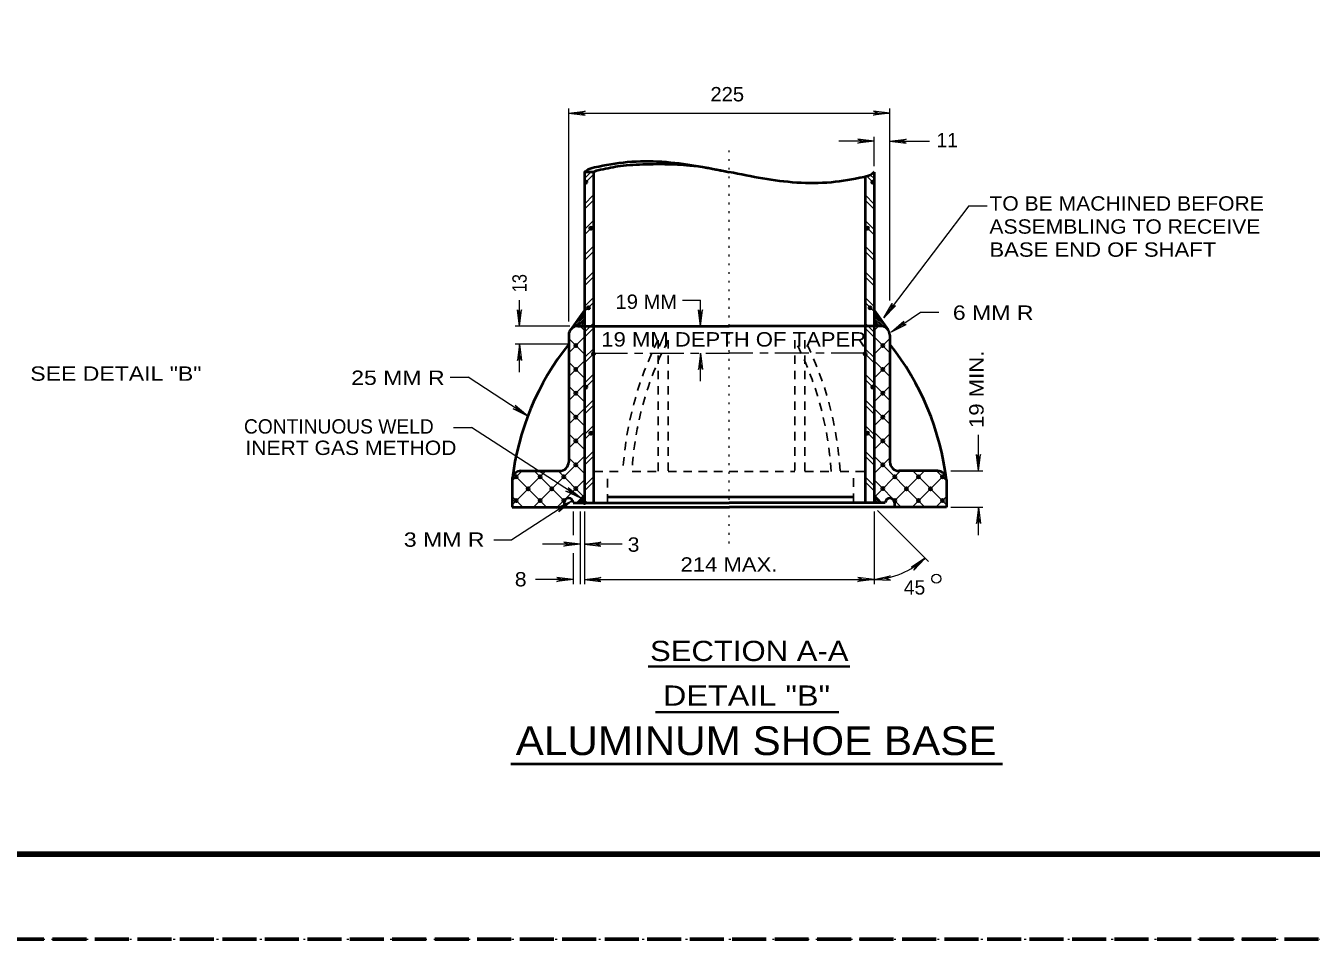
# Model space of a CAD drawing. Extents: x 312583 to 312854, y 144419 to 144597.
# Drawn here: x 312655 to 312723.1, y 144418.6 to 144466.9 of the extents above; entities that cross this region are included whole.
import ezdxf
from ezdxf.enums import TextEntityAlignment as Align

# ---------------------------------------------------------------- set-up
doc = ezdxf.new("R2010")
doc.units = 0
doc.header["$LTSCALE"] = 0.3
doc.header["$PDMODE"] = 32
doc.header["$PDSIZE"] = 0.15
for name, pattern in [('DOTTED', [1.5, 0.3, -1.2]), ('LONG_DASH_SHORT_DASH', [9.9, 6, -1.2, 1.5, -1.2]), ('LONG_DASHED', [7.5, 6, -1.5]), ('SHORT_DASHED', [2.7, 1.5, -1.2])]:
    doc.linetypes.add(name, pattern=pattern)
for name, color, linetype, lineweight in [('1', 7, 'Continuous', 35), ('2', 7, 'Continuous', 13), ('62', 7, 'DOTTED', 13), ('63', 7, 'LONG_DASHED', 60)]:
    doc.layers.add(name, color=color, linetype=linetype, lineweight=lineweight)

msp = doc.modelspace()

# ---------------------------------------------------------------- linework, layer by layer
at = {"layer": '1', "lineweight": 40}
for p, q in [((312684.6288, 144459.1856), (312684.6288, 144441.6903)), ((312685.1118, 144459.1856), (312684.6288, 144459.1856)), ((312685.1118, 144459.1856), (312685.1118, 144441.6903)), ((312699.9621, 144459.1856), (312699.9621, 144441.6903)), ((312699.4868, 144458.9326), (312699.4868, 144441.6903)), ((312684.6288, 144451.8716), (312683.8851, 144450.8366)), ((312699.9621, 144451.8716), (312700.7135, 144450.8366)), ((312684.2685, 144451.036), (312684.6288, 144451.036)), ((312684.6288, 144451.036), (312692.2955, 144451.036)), ((312699.9621, 144451.036), (312692.2955, 144451.036)), ((312700.3225, 144451.036), (312699.9621, 144451.036)), ((312683.7931, 144450.5606), (312683.7931, 144443.8523)), ((312700.7978, 144450.5606), (312700.7978, 144443.8523)), ((312680.7955, 144442.894), (312680.7955, 144441.4526)), ((312681.2785, 144443.3693), (312683.3101, 144443.3693)), ((312703.3201, 144443.3693), (312701.2808, 144443.3693)), ((312703.7955, 144442.894), (312703.7955, 144441.4526)), ((312684.2608, 144441.6903), (312684.6288, 144442.066)), ((312700.3301, 144441.6903), (312699.9621, 144442.066)), ((312680.7955, 144441.4526), (312692.2955, 144441.4526)), ((312683.5555, 144441.6903), (312683.5555, 144441.4526)), ((312684.0308, 144441.6903), (312692.2955, 144441.6903)), ((312685.8401, 144442.0046), (312698.8658, 144442.0046)), ((312700.5601, 144441.6903), (312692.2955, 144441.6903)), ((312703.7955, 144441.4526), (312692.2955, 144441.4526)), ((312701.0431, 144441.6903), (312701.0431, 144441.4526))]:
    msp.add_line(p, q, dxfattribs=at)
at = {"layer": '1', "lineweight": 13}
for p, q in [((312684.6288, 144458.8483), (312684.9661, 144459.1856)), ((312684.6288, 144458.58), (312685.1118, 144459.0553)), ((312699.9621, 144458.58), (312699.5941, 144458.948)), ((312699.9621, 144458.8483), (312699.7628, 144459.0476)), ((312684.6288, 144457.4913), (312685.1118, 144457.9743)), ((312699.9621, 144457.4913), (312699.4868, 144457.9743)), ((312684.6288, 144457.223), (312685.1118, 144457.706)), ((312699.9621, 144457.223), (312699.4868, 144457.706)), ((312684.6288, 144456.142), (312685.1118, 144456.6173)), ((312699.9621, 144456.142), (312699.4868, 144456.6173)), ((312684.6288, 144455.866), (312685.1118, 144456.349)), ((312699.9621, 144455.866), (312699.4868, 144456.349)), ((312684.6288, 144454.785), (312685.1118, 144455.2603)), ((312699.9621, 144454.785), (312699.4868, 144455.2603)), ((312684.6288, 144454.509), (312685.1118, 144454.992)), ((312699.9621, 144454.509), (312699.4868, 144454.992)), ((312684.6288, 144453.428), (312685.1118, 144453.911)), ((312684.6288, 144453.1596), (312685.1118, 144453.635)), ((312699.9621, 144453.428), (312699.4868, 144453.911)), ((312699.9621, 144453.1596), (312699.4868, 144453.635)), ((312684.6288, 144452.071), (312685.1118, 144452.554)), ((312684.6288, 144451.8026), (312685.1118, 144452.278)), ((312699.9621, 144452.071), (312699.4868, 144452.554)), ((312699.9621, 144451.8026), (312699.4868, 144452.278)), ((312684.6288, 144450.806), (312684.3988, 144451.036)), ((312684.6288, 144450.714), (312685.1041, 144451.197)), ((312684.6288, 144450.4456), (312685.1041, 144450.9286)), ((312699.9621, 144450.714), (312699.4868, 144451.197)), ((312699.9621, 144450.4456), (312699.4868, 144450.9286)), ((312699.9621, 144450.806), (312700.1921, 144451.036)), ((312683.7931, 144449.6176), (312684.6288, 144450.461)), ((312684.6288, 144449.541), (312683.7931, 144450.3843)), ((312700.7978, 144449.6176), (312699.9621, 144450.461)), ((312699.9621, 144449.541), (312700.7978, 144450.3843)), ((312684.6288, 144449.3646), (312685.1118, 144449.84)), ((312684.6288, 144449.0886), (312685.1118, 144449.5716)), ((312699.9621, 144449.3646), (312699.4868, 144449.84)), ((312699.9621, 144449.0886), (312699.4868, 144449.5716)), ((312683.7931, 144448.3603), (312684.6288, 144449.196)), ((312684.6288, 144448.2836), (312683.7931, 144449.1193)), ((312700.7978, 144448.3603), (312699.9621, 144449.196)), ((312699.9621, 144448.2836), (312700.7978, 144449.1193)), ((312684.6288, 144448.0076), (312685.1118, 144448.483)), ((312684.6288, 144447.7393), (312685.1118, 144448.2146)), ((312699.9621, 144448.0076), (312699.4868, 144448.483)), ((312699.9621, 144447.7393), (312699.4868, 144448.2146)), ((312683.7931, 144447.0953), (312684.6288, 144447.9386)), ((312684.6288, 144447.0186), (312683.7931, 144447.8543)), ((312700.7978, 144447.0953), (312699.9621, 144447.9386)), ((312699.9621, 144447.0186), (312700.7978, 144447.8543)), ((312684.6288, 144446.6506), (312685.1118, 144447.1336)), ((312684.6288, 144446.3823), (312685.1118, 144446.8576)), ((312699.9621, 144446.6506), (312699.4868, 144447.1336)), ((312699.9621, 144446.3823), (312699.4868, 144446.8576)), ((312683.7931, 144445.838), (312684.6288, 144446.6813)), ((312684.6288, 144445.7536), (312683.7931, 144446.597)), ((312700.7978, 144445.838), (312699.9621, 144446.6813)), ((312699.9621, 144445.7536), (312700.7978, 144446.597)), ((312684.6288, 144445.2936), (312685.1118, 144445.7766)), ((312684.6288, 144445.0253), (312685.1118, 144445.5083)), ((312699.9621, 144445.2936), (312699.4868, 144445.7766)), ((312699.9621, 144445.0253), (312699.4868, 144445.5083)), ((312683.7931, 144444.5806), (312684.6288, 144445.4163)), ((312684.6288, 144444.4963), (312683.7931, 144445.332)), ((312700.7978, 144444.5806), (312699.9621, 144445.4163)), ((312699.9621, 144444.4963), (312700.7978, 144445.332)), ((312681.9301, 144441.4526), (312684.6288, 144444.159)), ((312684.6288, 144443.9443), (312685.1118, 144444.4196)), ((312684.6288, 144443.6683), (312685.1118, 144444.1513)), ((312699.9621, 144443.9443), (312699.4868, 144444.4196)), ((312699.9621, 144443.6683), (312699.4868, 144444.1513)), ((312702.6608, 144441.4526), (312699.9621, 144444.159)), ((312684.6288, 144443.2313), (312683.7931, 144444.067)), ((312699.9621, 144443.2313), (312700.7978, 144444.067)), ((312680.7955, 144441.583), (312682.5818, 144443.3693)), ((312680.7955, 144442.8403), (312681.3245, 144443.3693)), ((312682.6201, 144441.4526), (312680.7955, 144443.2773)), ((312683.5631, 144441.767), (312681.9685, 144443.3693)), ((312683.1875, 144441.4526), (312684.6288, 144442.894)), ((312684.6288, 144441.9663), (312683.2258, 144443.3693)), ((312684.6288, 144442.5873), (312685.1118, 144443.0626)), ((312684.6288, 144442.3113), (312685.1118, 144442.7943)), ((312699.9621, 144442.5873), (312699.4868, 144443.0626)), ((312699.9621, 144442.3113), (312699.4868, 144442.7943)), ((312699.9621, 144441.9663), (312701.3651, 144443.3693)), ((312701.4035, 144441.4526), (312699.9621, 144442.894)), ((312701.0278, 144441.767), (312702.6301, 144443.3693)), ((312701.9785, 144441.4526), (312703.7955, 144443.2773)), ((312703.7955, 144441.583), (312702.0091, 144443.3693)), ((312703.7955, 144442.8403), (312703.2665, 144443.3693)), ((312681.3551, 144441.4526), (312680.7955, 144442.0123)), ((312685.0965, 144441.6903), (312685.1118, 144441.7133)), ((312699.5021, 144441.6903), (312699.4868, 144441.7133)), ((312703.2358, 144441.4526), (312703.7955, 144442.0123))]:
    msp.add_line(p, q, dxfattribs=at)
at = {"layer": '1', "lineweight": 25}
for p, q in [((312684.0078, 144451.013), (312684.6288, 144451.634)), ((312684.2531, 144451.3503), (312684.6288, 144451.726)), ((312684.4985, 144451.6876), (312684.6288, 144451.8256)), ((312700.1001, 144451.6876), (312699.9621, 144451.8256)), ((312700.3378, 144451.3503), (312699.9621, 144451.726)), ((312700.5831, 144451.013), (312699.9621, 144451.634)), ((312684.1075, 144451.0206), (312684.6288, 144451.542)), ((312684.2148, 144451.0283), (312684.6288, 144451.4423)), ((312684.3145, 144451.036), (312684.6288, 144451.3503)), ((312684.4141, 144451.036), (312684.6288, 144451.2583)), ((312684.5061, 144451.036), (312684.6288, 144451.1586)), ((312684.5981, 144451.036), (312684.6288, 144451.0666)), ((312700.4835, 144451.0206), (312699.9621, 144451.542)), ((312700.3761, 144451.0283), (312699.9621, 144451.4423)), ((312700.2765, 144451.036), (312699.9621, 144451.3503)), ((312700.1845, 144451.036), (312699.9621, 144451.2583)), ((312700.0848, 144451.036), (312699.9621, 144451.1586)), ((312699.9928, 144451.036), (312699.9621, 144451.0666)), ((312684.3451, 144441.698), (312684.6288, 144441.9816)), ((312684.4371, 144441.698), (312684.6288, 144441.8896)), ((312684.5291, 144441.698), (312684.6288, 144441.79)), ((312700.2535, 144441.698), (312699.9621, 144441.9816)), ((312700.1538, 144441.698), (312699.9621, 144441.8896)), ((312700.0618, 144441.698), (312699.9621, 144441.79)), ((312699.9698, 144441.698), (312699.9621, 144441.698))]:
    msp.add_line(p, q, dxfattribs=at)
at = {"layer": '1', "linetype": 'SHORT_DASHED', "lineweight": 25}
for p, q in [((312688.5235, 144450.2923), (312688.5235, 144443.3156)), ((312689.0601, 144450.2923), (312689.0601, 144443.3693)), ((312695.7685, 144450.2923), (312695.7685, 144443.3923)), ((312685.1501, 144443.3463), (312686.6375, 144443.3463)), ((312685.8401, 144441.6903), (312685.8401, 144443.285)), ((312687.1588, 144443.3463), (312688.5005, 144443.3463)), ((312689.0525, 144443.3463), (312695.7685, 144443.3463)), ((312698.1758, 144443.3463), (312699.4408, 144443.3463)), ((312698.8658, 144441.721), (312698.8658, 144443.331))]:
    msp.add_line(p, q, dxfattribs=at)
at = {"layer": '1', "linetype": 'LONG_DASH_SHORT_DASH', "lineweight": 13}
for p in [(312685.1118, 144449.6023), (312699.4868, 144449.6023)]:
    msp.add_line(p, (312692.2955, 144449.6023), dxfattribs=at)
at = {"layer": '1', "lineweight": 158}
msp.add_line((312616.5, 144423.0846), (312849, 144423.0846), dxfattribs=at)
at = {"layer": '1', "linetype": 'SHORT_DASHED', "lineweight": 25}
msp.add_lwpolyline([(312696.3051, 144450.2923), (312696.3051, 144443.3463), (312697.6851, 144443.3463)], dxfattribs=at)
at = {"layer": '1', "lineweight": 40}
for centre, radius, start, end in [((312684.2704, 144450.5568), 0.4792, 90, 180), ((312700.3206, 144450.5568), 0.4792, 0, 90), ((312694.908, 144441.2261), 14.2103, 141.47211, 173.27514), ((312689.6829, 144441.2261), 14.2103, 6.72486, 38.52789), ((312683.3121, 144443.8485), 0.4792, 270, 0), ((312701.2789, 144443.8485), 0.4792, 180, 270), ((312681.2746, 144442.8901), 0.4792, 90, 180), ((312703.3163, 144442.8901), 0.4792, 0, 90), ((312683.7912, 144441.6922), 0.2396, 0, 180), ((312700.7997, 144441.6922), 0.2396, 0, 180)]:
    msp.add_arc(centre, radius, start, end, dxfattribs=at)
at = {"layer": '1', "linetype": 'SHORT_DASHED', "lineweight": 25}
for centre, radius, start, end in [((312704.4129, 144442.3201), 17.781, 153.35491, 176.59885), ((312704.4129, 144442.3201), 17.3018, 152.55593, 176.59975), ((312680.4119, 144442.3201), 17.3018, 3.40025, 27.44407), ((312680.4119, 144442.3201), 17.781, 3.40115, 26.64509)]:
    msp.add_arc(centre, radius, start, end, dxfattribs=at)
at = {"layer": '1', "lineweight": 40}
for points in [[(312684.6288, 144459.1856), (312684.7285, 144459.2776), (312685.1578, 144459.4386), (312686.9058, 144459.7223), (312688.7305, 144459.7376), (312692.2955, 144459.1856)], [(312685.1118, 144459.1856), (312685.1961, 144459.2393), (312685.4798, 144459.316), (312686.5301, 144459.523), (312687.1895, 144459.5766), (312688.6155, 144459.615), (312689.6811, 144459.5843), (312690.4095, 144459.523), (312692.2955, 144459.1856)], [(312699.9621, 144459.1856), (312699.8625, 144459.086), (312699.4331, 144458.925), (312697.6851, 144458.6413), (312695.8681, 144458.626), (312692.2955, 144459.1856)]]:
    msp.add_spline(points, degree=3, dxfattribs=at)
at = {"layer": '1'}
for p in [(312684.6978, 144458.649), (312699.8931, 144458.649), (312684.9661, 144456.211), (312699.6248, 144456.211), (312684.8358, 144452.0096), (312699.7551, 144452.0096), (312684.1765, 144450.001), (312685.1041, 144449.564), (312699.4868, 144449.564), (312700.4221, 144450.001), (312684.1765, 144448.7436), (312700.4221, 144448.7436), (312684.1688, 144447.4786), (312684.6978, 144447.8083), (312699.8931, 144447.8083), (312700.4221, 144447.4786), (312684.1688, 144446.2136), (312700.4221, 144446.2136), (312684.1688, 144444.9563), (312684.9661, 144445.3626), (312699.6248, 144445.3626), (312700.4221, 144444.9563), (312684.1688, 144443.6913), (312700.4221, 144443.6913), (312681.0101, 144443.0626), (312682.2751, 144443.0626), (312683.5325, 144443.0626), (312701.0585, 144443.0626), (312702.3158, 144443.0626), (312703.5808, 144443.0626), (312681.6388, 144442.4263), (312682.9038, 144442.4263), (312684.1688, 144442.434), (312700.4298, 144442.434), (312701.6871, 144442.4263), (312702.9521, 144442.4263), (312681.0101, 144441.7976), (312682.2751, 144441.7976), (312683.5325, 144441.7976), (312684.6288, 144441.698), (312701.0585, 144441.7976), (312702.3235, 144441.7976), (312703.5808, 144441.7976)]:
    msp.add_point(p, dxfattribs=at)
at = {"layer": '2'}
for p, q in [((312683.7931, 144451.2736), (312683.7931, 144462.5513)), ((312700.7978, 144452.3853), (312700.7978, 144462.5513)), ((312683.7931, 144462.306), (312684.6595, 144462.4133)), ((312683.7931, 144462.306), (312700.7978, 144462.306)), ((312683.7931, 144462.306), (312684.6595, 144462.1986)), ((312684.6595, 144462.4133), (312684.3835, 144462.306)), ((312684.6595, 144462.1986), (312684.3835, 144462.306)), ((312699.9315, 144462.4133), (312700.2075, 144462.306)), ((312700.7978, 144462.306), (312699.9315, 144462.4133)), ((312699.9315, 144462.1986), (312700.2075, 144462.306)), ((312700.7978, 144462.306), (312699.9315, 144462.1986)), ((312699.9621, 144460.8186), (312698.0991, 144460.8186)), ((312699.0958, 144460.926), (312699.3718, 144460.8186)), ((312699.9621, 144460.8186), (312699.0958, 144460.926)), ((312699.0958, 144460.7113), (312699.3718, 144460.8186)), ((312699.9621, 144460.8186), (312699.0958, 144460.7113)), ((312699.9621, 144459.5), (312699.9621, 144461.0563)), ((312700.8055, 144460.8186), (312701.6718, 144460.926)), ((312700.8055, 144460.8186), (312702.9033, 144460.8186)), ((312700.8055, 144460.8186), (312701.6718, 144460.7113)), ((312701.6718, 144460.926), (312701.3958, 144460.8186)), ((312701.6718, 144460.7113), (312701.3958, 144460.8186)), ((312704.9915, 144457.3993), (312700.4835, 144451.473)), ((312704.9915, 144457.3993), (312705.9498, 144457.3993)), ((312681.1865, 144451.036), (312681.1865, 144452.416)), ((312689.8115, 144452.416), (312690.7698, 144452.416)), ((312690.7698, 144451.036), (312690.7698, 144452.416)), ((312681.0791, 144451.9023), (312681.1865, 144451.6263)), ((312681.1865, 144451.036), (312681.0791, 144451.9023)), ((312681.2938, 144451.9023), (312681.1865, 144451.6263)), ((312681.1865, 144451.036), (312681.2938, 144451.9023)), ((312690.6625, 144451.9023), (312690.7698, 144451.6263)), ((312690.7698, 144451.036), (312690.6625, 144451.9023)), ((312690.8771, 144451.9023), (312690.7698, 144451.6263)), ((312690.7698, 144451.036), (312690.8771, 144451.9023)), ((312700.4835, 144451.473), (312700.9205, 144452.232)), ((312700.4835, 144451.473), (312701.0968, 144452.1016)), ((312700.9205, 144452.232), (312700.8438, 144451.9406)), ((312701.0968, 144452.1016), (312700.8438, 144451.9406)), ((312683.8468, 144451.036), (312680.9488, 144451.036)), ((312700.8821, 144450.7293), (312701.5415, 144451.3043)), ((312700.8821, 144450.7293), (312701.6641, 144451.128)), ((312701.5415, 144451.3043), (312701.3728, 144451.059)), ((312701.6641, 144451.128), (312701.3728, 144451.059)), ((312683.8468, 144450.0776), (312680.9488, 144450.0776)), ((312681.1865, 144450.0776), (312681.0791, 144449.2113)), ((312681.1865, 144448.598), (312681.1865, 144450.0776)), ((312681.1865, 144450.0776), (312681.2938, 144449.2113)), ((312690.7698, 144449.6023), (312690.6625, 144448.736)), ((312690.7698, 144448.1226), (312690.7698, 144449.6023)), ((312690.7698, 144449.6023), (312690.8771, 144448.736)), ((312681.0791, 144449.2113), (312681.1865, 144449.4873)), ((312681.2938, 144449.2113), (312681.1865, 144449.4873)), ((312690.6625, 144448.736), (312690.7698, 144449.012)), ((312690.8771, 144448.736), (312690.7698, 144449.012)), ((312677.5141, 144448.3296), (312678.4725, 144448.3296)), ((312681.6311, 144446.275), (312678.4725, 144448.3296)), ((312680.9641, 144446.8346), (312681.1405, 144446.597)), ((312681.6311, 144446.275), (312680.9641, 144446.8346)), ((312680.8491, 144446.6583), (312681.1405, 144446.597)), ((312681.6311, 144446.275), (312680.8491, 144446.6583)), ((312677.6905, 144445.6693), (312678.6488, 144445.6693)), ((312684.4295, 144441.9203), (312678.6488, 144445.6693)), ((312705.4898, 144443.3693), (312705.4898, 144445.286)), ((312705.3825, 144444.2356), (312705.4898, 144443.9596)), ((312705.4898, 144443.3693), (312705.3825, 144444.2356)), ((312705.5971, 144444.2356), (312705.4898, 144443.9596)), ((312705.4898, 144443.3693), (312705.5971, 144444.2356)), ((312704.0331, 144443.3693), (312705.7275, 144443.3693)), ((312683.6475, 144442.296), (312683.9388, 144442.2423)), ((312684.4295, 144441.9203), (312683.6475, 144442.296)), ((312683.7625, 144442.48), (312683.9388, 144442.2423)), ((312684.4295, 144441.9203), (312683.7625, 144442.48)), ((312683.9388, 144441.7746), (312680.7801, 144439.72)), ((312683.9388, 144441.7746), (312683.1568, 144441.3913)), ((312683.1568, 144441.3913), (312683.4481, 144441.4526)), ((312683.9388, 144441.7746), (312683.2718, 144441.2073)), ((312683.2718, 144441.2073), (312683.4481, 144441.4526)), ((312704.0331, 144441.4526), (312705.7275, 144441.4526)), ((312705.4898, 144441.4526), (312705.3825, 144440.5863)), ((312705.4898, 144439.973), (312705.4898, 144441.4526)), ((312705.4898, 144441.4526), (312705.5971, 144440.5863)), ((312684.0308, 144441.215), (312684.0308, 144439.973)), ((312684.3911, 144441.215), (312684.3911, 144437.3816)), ((312684.6288, 144441.215), (312684.6288, 144437.3816)), ((312699.9621, 144441.215), (312699.9621, 144437.3816)), ((312700.1385, 144441.284), (312702.8448, 144438.5776)), ((312705.3825, 144440.5863), (312705.4898, 144440.8623)), ((312705.5971, 144440.5863), (312705.4898, 144440.8623)), ((312679.8218, 144439.72), (312680.7801, 144439.72)), ((312684.3911, 144439.4976), (312682.4055, 144439.4976)), ((312683.5248, 144439.605), (312683.8008, 144439.4976)), ((312684.3911, 144439.4976), (312683.5248, 144439.605)), ((312683.5248, 144439.3903), (312683.8008, 144439.4976)), ((312684.3911, 144439.4976), (312683.5248, 144439.3903)), ((312684.6288, 144439.4976), (312685.4951, 144439.605)), ((312686.6145, 144439.4976), (312684.6288, 144439.4976)), ((312684.6288, 144439.4976), (312685.4951, 144439.3903)), ((312685.4951, 144439.605), (312685.2191, 144439.4976)), ((312685.4951, 144439.3903), (312685.2191, 144439.4976)), ((312684.0308, 144439.0146), (312684.0308, 144437.3816)), ((312702.6685, 144438.7616), (312701.9401, 144438.271)), ((312702.6685, 144438.7616), (312702.0781, 144438.11)), ((312701.9401, 144438.271), (312702.2161, 144438.3706)), ((312702.0781, 144438.11), (312702.2161, 144438.3706)), ((312684.0308, 144437.6193), (312682.0375, 144437.6193)), ((312683.1645, 144437.7266), (312683.4405, 144437.6193)), ((312684.0308, 144437.6193), (312683.1645, 144437.7266)), ((312683.1645, 144437.512), (312683.4405, 144437.6193)), ((312684.0308, 144437.6193), (312683.1645, 144437.512)), ((312684.6288, 144437.6193), (312685.4951, 144437.7266)), ((312684.6288, 144437.6193), (312699.9621, 144437.6193)), ((312684.6288, 144437.6193), (312685.4951, 144437.512)), ((312685.4951, 144437.7266), (312685.2191, 144437.6193)), ((312685.4951, 144437.512), (312685.2191, 144437.6193)), ((312699.0958, 144437.7266), (312699.3718, 144437.6193)), ((312699.9621, 144437.6193), (312699.0958, 144437.7266)), ((312699.0958, 144437.512), (312699.3718, 144437.6193)), ((312699.9621, 144437.6193), (312699.0958, 144437.512)), ((312699.9621, 144437.6193), (312700.8131, 144437.811)), ((312699.9621, 144437.6193), (312700.8361, 144437.5963)), ((312700.8131, 144437.811), (312700.5525, 144437.673)), ((312700.8361, 144437.5963), (312700.5525, 144437.673))]:
    msp.add_line(p, q, dxfattribs=at)
at = {"layer": '2', "linetype": 'DOTTED'}
msp.add_line((312692.2955, 144439.536), (312692.2955, 144460.4966), dxfattribs=at)
at = {"layer": '2', "lineweight": 35}
for p, q in [((312687.9913, 144433.027), (312698.6758, 144433.027)), ((312688.3811, 144430.6005), (312698.09, 144430.6005))]:
    msp.add_line(p, q, dxfattribs=at)
at = {"layer": '2', "lineweight": 40}
msp.add_line((312680.7234, 144427.875), (312706.7674, 144427.875), dxfattribs=at)
at = {"layer": '2'}
msp.add_lwpolyline([(312700.8821, 144450.7293), (312702.4308, 144451.7796), (312703.3891, 144451.7796)], dxfattribs=at)
msp.add_circle((312703.2626, 144437.6672), 0.2351, dxfattribs=at)
msp.add_arc((312699.7822, 144441.8231), 4.2077, 272.45055, 313.23855, dxfattribs=at)
at = {"layer": '62'}
msp.add_lwpolyline([(312601.2, 144418.5846), (312853.5, 144418.5846), (312853.5, 144596.7846)], dxfattribs=at)
at = {"layer": '63'}
msp.add_line((312851.75, 144418.5846), (312583.526, 144418.5846), dxfattribs=at)

# ---------------------------------------------------------------- texts
at = {"layer": '2'}
for s, width, p in [('225', 1.05, (312691.2982, 144462.928)), ('TO BE MACHINED BEFORE', 1.1, (312706.0725, 144457.1453)), ('ASSEMBLING TO RECEIVE', 1.1, (312706.0725, 144455.9253)), ('BASE END OF SHAFT', 1.15, (312706.0725, 144454.7053)), ('19 MM', 1.05, (312686.2717, 144451.9473)), ('6 MM R', 1.2, (312704.1361, 144451.3666)), ('19 MM DEPTH OF TAPER', 1.15, (312685.5165, 144449.9541)), ('SEE DETAIL "B"', 1.2, (312655.2737, 144448.1427)), ('25 MM R', 1.2, (312672.2714, 144447.9222)), ('INERT GAS METHOD', 1.1, (312666.6658, 144444.2145)), ('3 MM R', 1.2, (312675.0605, 144439.3558)), ('3 ', 1.1, (312686.9154, 144439.0941)), ('214 MAX.', 1.15, (312689.7127, 144438.0383)), ('8 ', 1.1, (312680.9377, 144437.259))]:
    msp.add_text(s, height=0.76, dxfattribs=dict(at, width=width)).set_placement(p)
for s, p in [('11 ', (312703.2775, 144460.5014)), ('CONTINUOUS WELD', (312666.5924, 144445.3463)), ('45', (312701.5438, 144436.8268))]:
    msp.add_text(s, height=0.76, dxfattribs=at).set_placement(p)
for s, width, p in [('13', 0.85, (312681.5638, 144452.8277)), ('19 MIN.', 1.15, (312705.7665, 144445.6439))]:
    msp.add_text(s, height=0.76, rotation=90, dxfattribs=dict(at, width=width)).set_placement(p)
for s, height, width, p in [('SECTION A-A', 1.07, 1.15, (312693.3547, 144433.3095)), ('DETAIL "B"', 1.07, 1.2, (312693.2077, 144430.9451)), ('ALUMINUM SHOE BASE', 1.52, 1.1, (312693.718, 144428.3323))]:
    msp.add_text(s, height=height, dxfattribs=dict(at, width=width)).set_placement(p, align=Align.CENTER)

doc.saveas('drawing.dxf')
